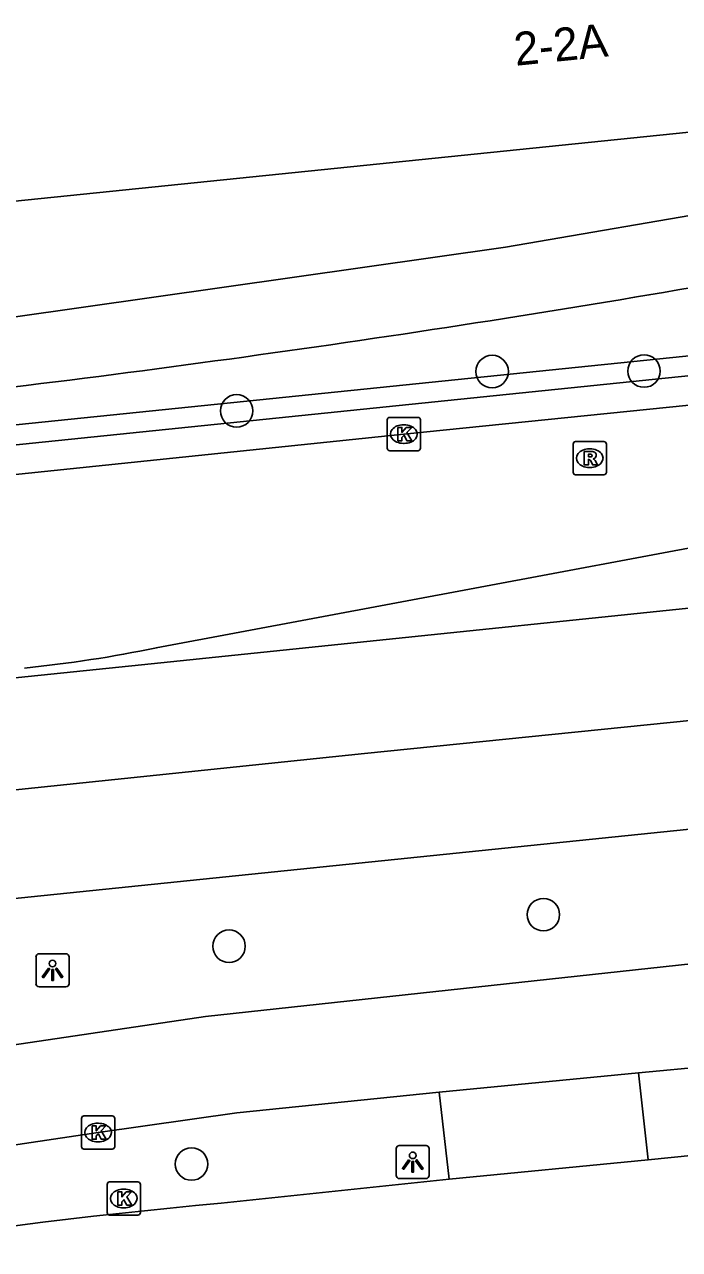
# Model space of a CAD drawing. Extents: x 160676 to 161153, y 383244 to 383713.
# Drawn here: x 161034.9 to 161054.61, y 383550.95 to 383587.82 of the extents above; entities that cross this region are included whole.
import ezdxf

# ---------------------------------------------------------------- set-up
doc = ezdxf.new("R2010")
doc.units = 0
for name, color, linetype in [('IMGEO_Boom', 7, 'Continuous'), ('IMGEO_Fietspad_gesloten', 7, 'Continuous'), ('IMGEO_Haag', 7, 'Continuous'), ('IMGEO_Kolk', 7, 'Continuous'), ('IMGEO_Lichtpunt', 7, 'Continuous'), ('IMGEO_OVBaan_gesloten', 7, 'Continuous'), ('IMGEO_Pand', 7, 'Continuous'), ('IMGEO_Pand_nummerreeks', 7, 'Continuous'), ('IMGEO_Rijbaan_lokaal_gesloten', 7, 'Continuous'), ('IMGEO_Rioolput', 7, 'Continuous'), ('IMGEO_Voetpad_open', 7, 'Continuous')]:
    doc.layers.add(name, color=color, linetype=linetype)

msp = doc.modelspace()

# ---------------------------------------------------------------- linework, layer by layer
at = {"layer": 'IMGEO_Boom'}
for centre in [(161053.538, 383577.393), (161048.966, 383577.378), (161041.279, 383576.195), (161050.51, 383561.032), (161041.05, 383560.082), (161039.921, 383553.526)]:
    msp.add_circle(centre, 0.489, dxfattribs=at)
at = {"layer": 'IMGEO_Fietspad_gesloten'}
for points in [[(161000.877, 383575.549), (161009.712, 383576.451), (161032.513, 383578.778), (161034.486, 383579.01), (161049.373, 383581.126), (161056.263, 383582.305)], [(161053.666, 383553.653), (161130.013, 383561.398)], [(161047.67, 383553.068), (161053.666, 383553.653)], [(161047.67, 383553.068), (161040.812, 383552.349)]]:
    msp.add_lwpolyline(points, dxfattribs=at)
for centre, radius, start, end in [((160983.214, 383998.386), 424.589, 276.28566, 280.08898), ((161057.89, 383367.369), 185.767, 95.27481, 102.885)]:
    msp.add_arc(centre, radius, start, end, dxfattribs=at)
at = {"layer": 'IMGEO_Haag'}
msp.add_lwpolyline([(161056.42, 383577.406), (161056.389, 383577.704), (161056.358, 383578.002), (161013.777, 383573.636), (161013.808, 383573.338), (161013.839, 383573.04), (161056.42, 383577.406)], dxfattribs=at)
at = {"layer": 'IMGEO_Kolk'}
for p, q in [((161045.81, 383575.071), (161045.81, 383575.923)), ((161045.885, 383575.997), (161046.737, 383575.997)), ((161046.298, 383575.777), (161046.323, 383575.777)), ((161046.811, 383575.923), (161046.811, 383575.071)), ((161046.737, 383574.997), (161045.885, 383574.997)), ((161046.321, 383575.217), (161046.296, 383575.217)), ((161036.609, 383554.048), (161036.609, 383554.9)), ((161036.684, 383554.974), (161037.536, 383554.974)), ((161037.097, 383554.754), (161037.122, 383554.754)), ((161037.61, 383554.9), (161037.61, 383554.048)), ((161037.536, 383553.974), (161036.684, 383553.974)), ((161037.12, 383554.194), (161037.095, 383554.194)), ((161037.381, 383552.063), (161037.381, 383552.915)), ((161037.456, 383552.989), (161038.308, 383552.989)), ((161038.382, 383552.915), (161038.382, 383552.063)), ((161037.869, 383552.769), (161037.894, 383552.769)), ((161037.892, 383552.209), (161037.867, 383552.209)), ((161038.308, 383551.989), (161037.456, 383551.989))]:
    msp.add_line(p, q, dxfattribs=at)
for points in [[(161045.81, 383575.071), (161045.81, 383575.923)], [(161045.885, 383575.997), (161046.737, 383575.997)], [(161046.131, 383575.697), (161046.254, 383575.697), (161046.254, 383575.546), (161046.384, 383575.697), (161046.548, 383575.697), (161046.402, 383575.546), (161046.555, 383575.297), (161046.403, 383575.297), (161046.318, 383575.461), (161046.254, 383575.394), (161046.254, 383575.297), (161046.131, 383575.297), (161046.131, 383575.697)], [(161046.811, 383575.923), (161046.811, 383575.071)], [(161046.737, 383574.997), (161045.885, 383574.997)], [(161036.609, 383554.048), (161036.609, 383554.9)], [(161036.684, 383554.974), (161037.536, 383554.974)], [(161036.93, 383554.674), (161037.053, 383554.674), (161037.053, 383554.523), (161037.183, 383554.674), (161037.347, 383554.674), (161037.201, 383554.523), (161037.354, 383554.274), (161037.202, 383554.274), (161037.117, 383554.438), (161037.053, 383554.371), (161037.053, 383554.274), (161036.93, 383554.274), (161036.93, 383554.674)], [(161037.61, 383554.9), (161037.61, 383554.048)], [(161037.536, 383553.974), (161036.684, 383553.974)], [(161037.381, 383552.063), (161037.381, 383552.915)], [(161037.456, 383552.989), (161038.308, 383552.989)], [(161038.382, 383552.915), (161038.382, 383552.063)], [(161037.702, 383552.689), (161037.825, 383552.689), (161037.825, 383552.538), (161037.955, 383552.689), (161038.119, 383552.689), (161037.973, 383552.538), (161038.126, 383552.289), (161037.974, 383552.289), (161037.889, 383552.453), (161037.825, 383552.386), (161037.825, 383552.289), (161037.702, 383552.289), (161037.702, 383552.689)], [(161038.308, 383551.989), (161037.456, 383551.989)]]:
    msp.add_lwpolyline(points, dxfattribs=at)
for centre, start, end in [((161045.887, 383575.921), 91.552, 178.448), ((161045.887, 383575.921), 91.552, 178.448), ((161046.735, 383575.921), 1.552, 88.448), ((161046.735, 383575.921), 1.552, 88.448), ((161045.887, 383575.073), 181.552, 268.448), ((161045.887, 383575.073), 181.552, 268.448), ((161046.735, 383575.073), 271.552, 358.448), ((161046.735, 383575.073), 271.552, 358.448), ((161036.686, 383554.898), 91.552, 178.448), ((161036.686, 383554.898), 91.552, 178.448), ((161037.534, 383554.898), 1.552, 88.448), ((161037.534, 383554.898), 1.552, 88.448), ((161036.686, 383554.05), 181.552, 268.448), ((161036.686, 383554.05), 181.552, 268.448), ((161037.534, 383554.05), 271.552, 358.448), ((161037.534, 383554.05), 271.552, 358.448), ((161037.458, 383552.913), 91.552, 178.448), ((161037.458, 383552.913), 91.552, 178.448), ((161038.306, 383552.913), 1.552, 88.448), ((161038.306, 383552.913), 1.552, 88.448), ((161037.458, 383552.065), 181.552, 268.448), ((161037.458, 383552.065), 181.552, 268.448), ((161038.306, 383552.065), 271.552, 358.448), ((161038.306, 383552.065), 271.552, 358.448)]:
    msp.add_arc(centre, 0.0765, start, end, dxfattribs=at)
for centre, major_axis, ratio, start_param, end_param in [((161046.297, 383575.497), (-0.387, 0.002), 0.722429, 4.712389, 7.853982), ((161046.322, 383575.497), (-0.39, 0.002), 0.717154, 1.570796, 4.712389), ((161037.096, 383554.474), (-0.387, 0.002), 0.722429, 4.712389, 7.853982), ((161037.121, 383554.474), (-0.39, 0.002), 0.717154, 1.570796, 4.712389), ((161037.868, 383552.489), (-0.387, 0.002), 0.722429, 4.712389, 7.853982), ((161037.893, 383552.489), (-0.39, 0.002), 0.717154, 1.570796, 4.712389)]:
    msp.add_ellipse(centre, major_axis=major_axis, ratio=ratio, start_param=start_param, end_param=end_param, dxfattribs=at)
at = {"layer": 'IMGEO_Lichtpunt'}
for p, q in [((161036.143, 383559.856), (161035.335, 383559.856)), ((161036.143, 383559.856), (161035.335, 383559.856)), ((161035.241, 383559.761), (161035.241, 383558.954)), ((161035.241, 383559.761), (161035.241, 383558.954)), ((161036.237, 383558.954), (161036.237, 383559.761)), ((161036.237, 383558.954), (161036.237, 383559.761)), ((161035.335, 383558.86), (161036.143, 383558.86)), ((161035.335, 383558.86), (161036.143, 383558.86)), ((161046.078, 383553.99), (161046.078, 383553.183)), ((161046.078, 383553.99), (161046.078, 383553.183)), ((161046.98, 383554.085), (161046.172, 383554.085)), ((161046.98, 383554.085), (161046.172, 383554.085)), ((161047.074, 383553.183), (161047.074, 383553.99)), ((161047.074, 383553.183), (161047.074, 383553.99)), ((161046.172, 383553.089), (161046.98, 383553.089)), ((161046.172, 383553.089), (161046.98, 383553.089))]:
    msp.add_line(p, q, dxfattribs=at)
for points in [[(161035.615, 383559.425), (161035.654, 383559.397), (161035.466, 383559.135), (161035.428, 383559.162), (161035.615, 383559.425)], [(161035.717, 383559.377), (161035.764, 383559.377), (161035.764, 383559.055), (161035.717, 383559.055), (161035.717, 383559.377)], [(161035.827, 383559.397), (161035.865, 383559.424), (161036.052, 383559.162), (161036.013, 383559.134), (161035.827, 383559.397)], [(161046.452, 383553.654), (161046.491, 383553.626), (161046.303, 383553.364), (161046.265, 383553.391), (161046.452, 383553.654)], [(161046.554, 383553.606), (161046.601, 383553.606), (161046.601, 383553.284), (161046.554, 383553.284), (161046.554, 383553.606)], [(161046.664, 383553.626), (161046.702, 383553.653), (161046.889, 383553.391), (161046.85, 383553.363), (161046.664, 383553.626)]]:
    msp.add_lwpolyline(points, dxfattribs=at)
for centre in [(161035.74, 383559.559), (161046.577, 383553.788)]:
    msp.add_circle(centre, 0.0994, dxfattribs=at)
for centre, start, end in [((161035.335, 383559.761), 90, 180), ((161035.335, 383559.761), 90, 180), ((161036.143, 383559.761), 0, 90), ((161036.143, 383559.761), 0, 90), ((161035.335, 383558.954), 180, 270), ((161035.335, 383558.954), 180, 270), ((161036.143, 383558.954), 270, 0), ((161036.143, 383558.954), 270, 360), ((161046.172, 383553.99), 90, 180), ((161046.172, 383553.99), 90, 180), ((161046.98, 383553.99), 0, 90), ((161046.98, 383553.99), 0, 90), ((161046.172, 383553.183), 180, 270), ((161046.172, 383553.183), 180, 270), ((161046.98, 383553.183), 270, 0), ((161046.98, 383553.183), 270, 360)]:
    msp.add_arc(centre, 0.0946, start, end, dxfattribs=at)
at = {"layer": 'IMGEO_OVBaan_gesloten'}
for points in [[(161128.738, 383574.467), (161099.72, 383571.421), (161045.124, 383565.881), (161015.167, 383562.758)], [(161015.019, 383566.144), (161038.417, 383568.551), (161084.138, 383573.282)], [(161015.36, 383559.547), (161128.627, 383571.185)]]:
    msp.add_lwpolyline(points, dxfattribs=at)
at = {"layer": 'IMGEO_Pand'}
msp.add_lwpolyline([(161076.456, 383586.789), (161027.74, 383581.8)], dxfattribs=at)
at = {"layer": 'IMGEO_Rijbaan_lokaal_gesloten'}
for points in [[(161014.164, 383572.163), (161017.538, 383572.511), (161031.914, 383573.995), (161046.311, 383575.497), (161055.488, 383576.424)], [(161083.912, 383576.034), (161067.416, 383574.334), (161065.429, 383574.038), (161038.862, 383569.063)], [(161129.447, 383567.638), (161040.346, 383557.963), (161015.911, 383554.341)], [(161053.368, 383556.276), (161055.51, 383556.475), (161070.913, 383558.041), (161089.308, 383559.955), (161106.689, 383561.735), (161127.623, 383563.879), (161129.727, 383564.069)], [(161053.368, 383556.276), (161047.377, 383555.685)], [(161020.774, 383552.039), (161037.11, 383554.474), (161041.284, 383555.065), (161047.377, 383555.685)]]:
    msp.add_lwpolyline(points, dxfattribs=at)
msp.add_arc((161031.012, 383606.975), 38.716, 275.7566, 281.6988, dxfattribs=at)
at = {"layer": 'IMGEO_Rioolput'}
for p, q in [((161051.404, 383574.345), (161051.404, 383575.197)), ((161051.479, 383575.271), (161052.331, 383575.271)), ((161051.892, 383575.051), (161051.917, 383575.051)), ((161052.405, 383575.197), (161052.405, 383574.345)), ((161052.331, 383574.271), (161051.479, 383574.271)), ((161051.915, 383574.491), (161051.89, 383574.491))]:
    msp.add_line(p, q, dxfattribs=at)
for points in [[(161051.404, 383574.345), (161051.404, 383575.197)], [(161051.479, 383575.271), (161052.331, 383575.271)], [(161051.993, 383574.969), (161051.741, 383574.971), (161051.741, 383574.571)], [(161052.405, 383575.197), (161052.405, 383574.345)], [(161051.741, 383574.571), (161051.865, 383574.571), (161051.865, 383574.733), (161051.876, 383574.733)], [(161051.919, 383574.89), (161051.865, 383574.89), (161051.865, 383574.809)], [(161051.865, 383574.809), (161051.917, 383574.809)], [(161051.923, 383574.704), (161051.994, 383574.571), (161052.134, 383574.571), (161052.069, 383574.697)], [(161052.331, 383574.271), (161051.479, 383574.271)]]:
    msp.add_lwpolyline(points, dxfattribs=at)
for centre, radius, start, end in [((161051.481, 383575.195), 0.0765, 91.552, 178.448), ((161051.481, 383575.195), 0.0765, 91.552, 178.448), ((161051.992, 383574.859), 0.109, 350.3612, 89.416), ((161052.329, 383575.195), 0.0765, 1.552, 88.448), ((161052.329, 383575.195), 0.0765, 1.552, 88.448), ((161051.875, 383574.68), 0.0533, 26.0293, 88.6989), ((161051.901, 383574.998), 0.19, 274.7715, 282.9687), ((161051.925, 383574.794), 0.0964, 77.0061, 93.1865), ((161051.939, 383574.851), 0.0378, 276.6634, 79.6772), ((161051.99, 383574.859), 0.112, 277.5842, 350.9817), ((161051.974, 383574.644), 0.108, 29.5134, 73.7905), ((161051.481, 383574.347), 0.0765, 181.552, 268.448), ((161051.481, 383574.347), 0.0765, 181.552, 268.448), ((161052.329, 383574.347), 0.0765, 271.552, 358.448), ((161052.329, 383574.347), 0.0765, 271.552, 358.448)]:
    msp.add_arc(centre, radius, start, end, dxfattribs=at)
for centre, major_axis, ratio, start_param, end_param in [((161051.891, 383574.771), (-0.387, 0.002), 0.722429, 4.712389, 7.853982), ((161051.916, 383574.771), (-0.39, 0.002), 0.717154, 1.570796, 4.712389)]:
    msp.add_ellipse(centre, major_axis=major_axis, ratio=ratio, start_param=start_param, end_param=end_param, dxfattribs=at)
at = {"layer": 'IMGEO_Voetpad_open'}
for points in [[(161053.666, 383553.653), (161053.368, 383556.276)], [(161047.377, 383555.685), (161047.67, 383553.068)]]:
    msp.add_lwpolyline(points, dxfattribs=at)

# ---------------------------------------------------------------- texts
at = {"layer": 'IMGEO_Pand_nummerreeks'}
msp.add_text('2-2A', height=1, rotation=5.8473, dxfattribs=at).set_placement((161049.677, 383586.58))

doc.saveas('drawing.dxf')
